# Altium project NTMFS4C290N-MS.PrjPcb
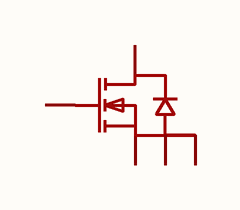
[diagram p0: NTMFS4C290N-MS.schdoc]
1 sheet, 1 parts. Net scope: global (net labels, ports and power ports of the same name join across sheets).

## Sheet NTMFS4C290N-MS.schdoc
size 127 x 101 mm

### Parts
Q?  ntmfs4c290n-ms  [TDSON-8_L5.9-W5.2-P1.27-BL-1]  (value not drawn)

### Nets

Not connected (* = marked no-connect by the designer): Q? 1(S) 2(S) 3(S) 4(G) 5(D)

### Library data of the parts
Q? = ntmfs4c290n-ms: 数量:1个N沟道;漏源电压(Vdss):30V;连续漏极电流(Id):80A;导通电阻(RDS(on)):4.7mΩ@10V;耗散功率(Pd):37W;阈值电压(Vgs(th)):1.7V;; Manufacturer: MSKSEMI(美森科); AddInBom: yes; ModelId: 6d3ef2b64d5a4f2dbd2ee02e0c7053d2; ModelTransform: 205.511,242.1255,0,0,0,0,0,42.913,0; Number: 1个N沟道; Drain to Source Voltage: 30V; Current - Continuous Drain(Id): 80A; Pd - Power Dissipation: 37W; Gate Threshold Voltage (Vgs(th)): 1.7V; Gate Charge(Qg): 38nC; Input Capacitance(Ciss): 1.93nF; Reverse Transfer Capacitance (Crss@Vds): 260pF; Configuration: 独立式; Type: N沟道; Output Capacitance(Coss): 310pF; Vgs: ±20V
